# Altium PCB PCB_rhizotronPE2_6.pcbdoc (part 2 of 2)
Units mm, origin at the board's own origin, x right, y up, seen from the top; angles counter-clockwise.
Board outline 141.81 x 99.53 mm, 2 copper layers (Top Layer, Bottom Layer); 83 components, 239 nets, 496 pads, 263 vias.
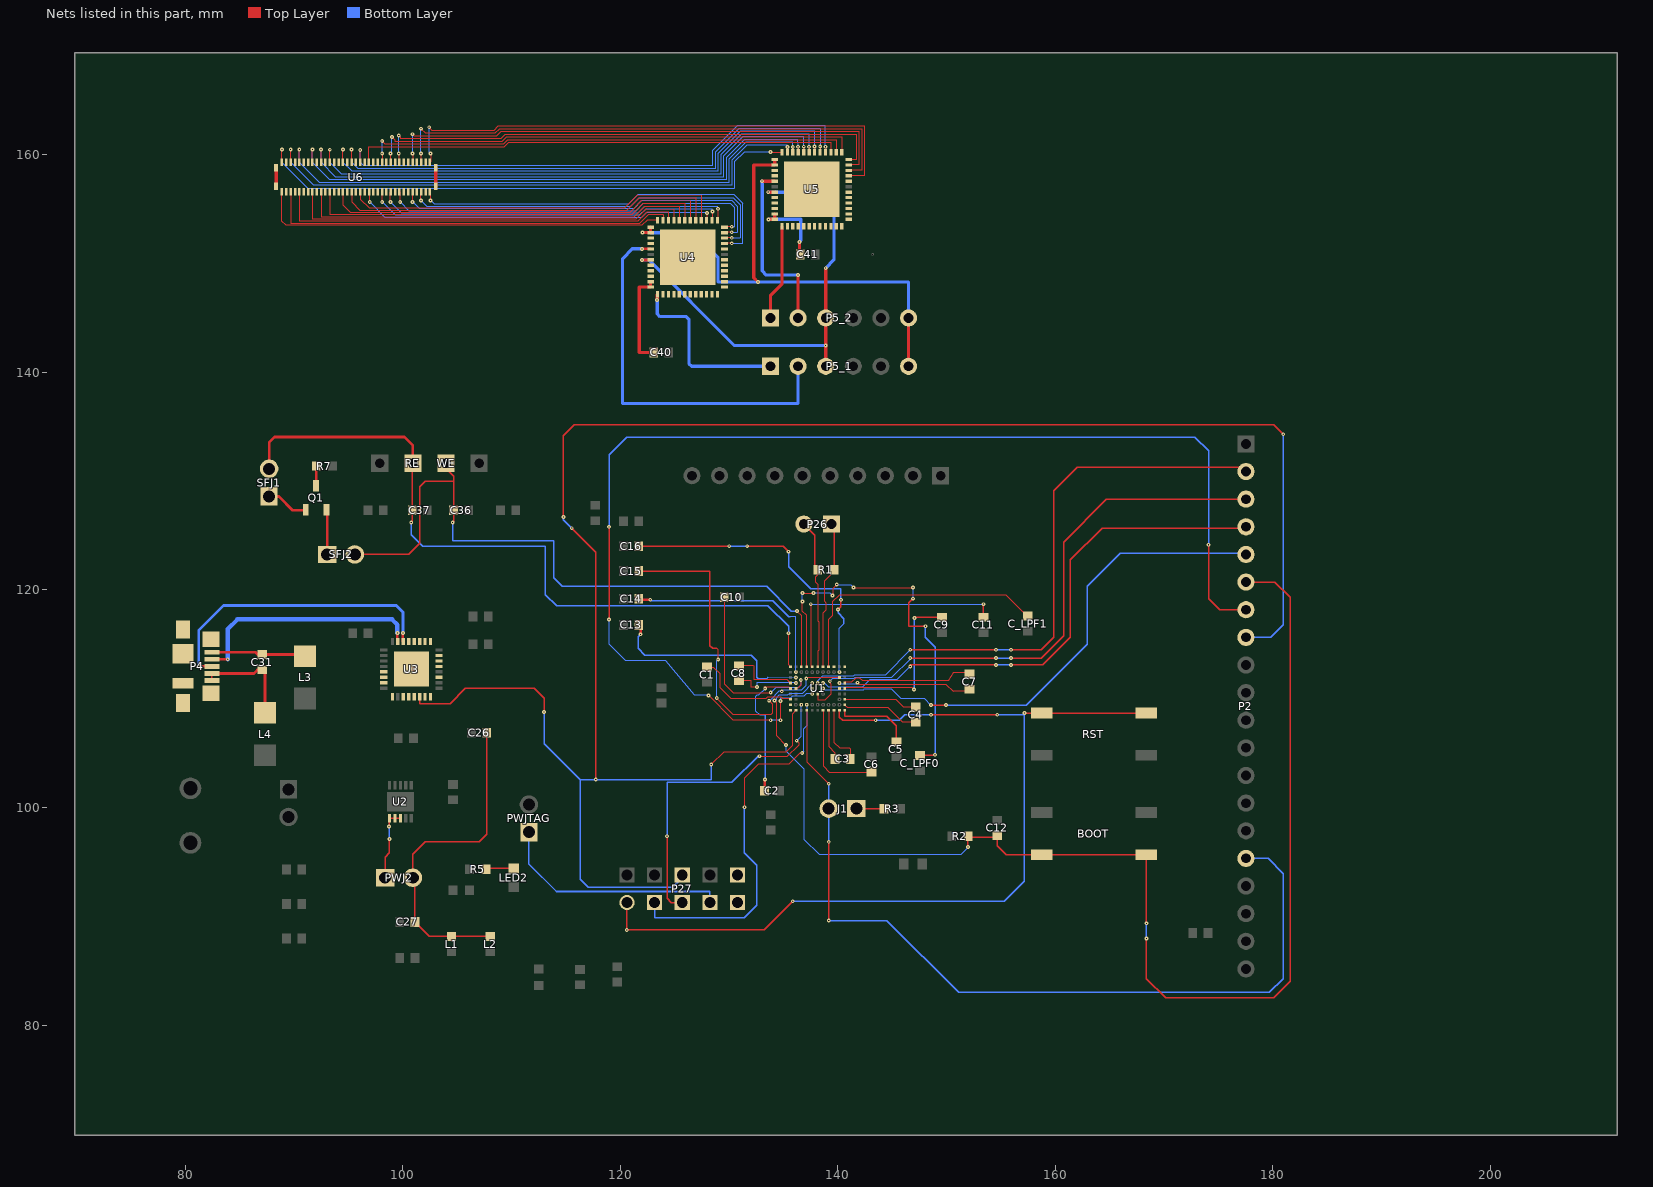
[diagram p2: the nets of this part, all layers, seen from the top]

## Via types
v1: diameter 0.35, hole 0.1, Top Layer to Bottom Layer, 263 vias

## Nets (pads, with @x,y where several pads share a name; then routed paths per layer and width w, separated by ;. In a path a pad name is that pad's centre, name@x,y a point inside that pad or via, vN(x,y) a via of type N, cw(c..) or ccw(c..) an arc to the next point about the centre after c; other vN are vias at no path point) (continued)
P0.11_SIN: P2.8 P27.6 U1.J2 U3.30 | length 187.6
  Top Layer w0.1: v1(128.369,103.953) 129.512,105.096 135.227,105.096 135.796,105.665 135.796,108.586 U1.J2@136.148,108.938
  Top Layer w0.125: U3.30@101.56,110.176 101.559,109.554 104.366,109.541 105.763,110.938 112.113,110.938 113.002,110.049 v1(113.002,108.779) ; v1(114.78,126.686) 114.78,134.179 115.796,135.195 180.058,135.195 v1(180.947,134.306) ; v1(115.542,125.67) 117.746,123.465 v1(117.746,102.556)
  Bottom Layer w0.125: v1(113.002,108.779) 113.002,105.858 116.304,102.556 ; v1(114.78,126.686) 114.78,126.432 v1(115.542,125.67) ; P27.6@125.702,93.793 125.702,93.539 124.813,92.65 117.066,92.65 116.304,93.412 116.304,102.556 ; v1(128.369,103.953) 128.369,102.556 v1(117.746,102.556) 116.304,102.556 ; P2.8@177.518,115.637 179.804,115.637 180.947,116.78 v1(180.947,134.306)
P1.0: P2.7 U1.F5 | length 115.1
  Top Layer w0.1: v1(128.115,110.303) 130.401,108.017 v1(133.83,108.017) ; v1(134.719,108.017) v1@134.719,109.795
  Top Layer w0.125: v1(118.971,117.288) v1(118.971,125.797) ; v1(174.089,124.146) 174.089,119.193 175.105,118.177 P2.7@177.518,118.177
  Bottom Layer w0.1: v1(118.971,117.288) 118.971,115.002 120.495,113.478 124.178,113.478 126.845,110.303 127.099,110.303 v1(128.115,110.303) ; v1(133.83,108.017) v1(134.719,108.017) ; v1@134.719,109.795 134.719,110.049 135.647,110.049 135.833,110.236 136.89,110.236 137.092,110.438 U1.F5@137.648,110.438
  Bottom Layer w0.125: v1(118.971,125.797) 118.971,132.401 120.622,134.052 172.819,134.052 174.089,132.782 v1(174.089,124.146)
  other v1: 134.719,109.786
P1.1: BOOT.1 BOOT.2 C12.2 P2.6 R2.1 U1.D5 | length 118.6
  Top Layer w0.1: v1(134.187,109.819) 134.338,109.668 134.338,106.62 v1(135.227,105.731)
  Top Layer w0.125: v1@151.967,96.357 151.967,97.246 154.493,97.246 C12.2@154.658,97.411 154.658,96.46 155.465,95.653 BOOT.2@158.748,95.653 BOOT.1@168.348,95.653 168.348,89.374 v1(168.374,89.348) ; v1(168.374,87.951) 168.374,84.268 170.152,82.49 180.058,82.49 181.582,84.014 181.582,119.32 180.185,120.717 P2.6@177.518,120.717
  Bottom Layer w0.1: v1(134.187,109.819) 134.238,109.819 134.338,109.919 134.338,110.049 134.592,110.303 135.354,110.303 135.524,110.473 136.727,110.473 137.648,111.394 U1.D5@137.648,111.438 ; v1(135.227,105.731) 135.227,105.223 136.878,103.572 136.878,97.095 138.275,95.698 151.356,95.698 151.968,96.31 v1(151.967,96.357)
  Bottom Layer w0.125: v1(168.374,87.951) v1(168.374,89.348)
P1.2_SCLK1: P2.5 U1.E7 | length 48.5
  Top Layer w0.125: v1(148.562,109.414) v1(149.959,109.414)
  Bottom Layer w0.1: U1.E7@138.648,110.938 138.748,110.838 142.383,110.838 142.438,110.893 144.924,110.893 145.768,110.049 147.927,110.049 v1(148.562,109.414)
  Bottom Layer w0.125: v1(149.959,109.414) 157.325,109.414 162.913,115.002 162.913,120.336 165.961,123.384 177.391,123.384 P2.5@177.518,123.257
P1.3_MOSI1: P2.4 U1.D7 | length 49.3
  Top Layer w0.125: v1(146.657,112.97) 146.657,113.097 v1(154.531,113.097) ; v1(155.928,113.097) 158.849,113.097 161.389,115.637 161.389,122.749 164.31,125.67 177.391,125.67 P2.4@177.518,125.797
  Bottom Layer w0.1: U1.D7@138.648,111.438 138.791,111.438 139.116,111.113 142.308,111.113 142.962,111.766 145.453,111.766 v1(146.657,112.97)
  Bottom Layer w0.125: v1(154.531,113.097) v1(155.928,113.097)
P1.4_MISO1: P2.3 U1.F6 | length 53.5
  Top Layer w0.1: U1.F6@138.148,110.438 138.148,109.909 138.849,109.909 139.394,110.454 139.394,111.343 139.267,111.469 v1(139.267,111.597)
  Top Layer w0.125: v1(146.657,113.732) v1(154.531,113.732) ; v1(155.928,113.732) 158.722,113.732 160.754,115.764 160.754,124.4 164.691,128.337 P2.3@177.518,128.337
  Bottom Layer w0.1: v1(139.267,111.597) 139.536,111.866 141.509,111.866 141.61,111.967 144.971,111.967 v1@146.741,113.737
  Bottom Layer w0.125: v1(154.531,113.732) v1(155.928,113.732)
P1.5_CS: P2.2 U1.D6 | length 55.8
  Top Layer w0.125: v1(146.657,114.494) v1(154.531,114.494) ; v1(155.928,114.494) 158.722,114.494 159.865,115.637 159.865,129.099 162.024,131.258 177.137,131.258 P2.2@177.518,130.877
  Bottom Layer w0.1: U1.D6@138.148,111.438 138.124,111.462 138.124,111.607 138.583,112.067 141.427,112.067 141.527,112.167 144.35,112.167 v1(146.657,114.494)
  Bottom Layer w0.125: v1(154.531,114.494) v1(155.928,114.494)
P2.4: J1.2 P2.16 U1.J4 | length 78.9
  Top Layer w0.1: U1.J4@137.148,108.938 137.147,104.192 v1(139.164,102.175)
  Top Layer w0.125: v1(139.164,89.602) v1(139.164,96.841)
  Bottom Layer w0.125: v1(139.164,89.602) 144.498,89.602 151.102,82.998 179.677,82.998 180.947,84.268 180.947,93.92 179.55,95.317 P2.16@177.518,95.317 ; v1(139.164,96.841) J1.2@139.164,99.889 v1(139.164,102.175)
P4_1: C31.2 L3.1 P4.1 | length 8.7
  Top Layer w0.254: P4.1@82.467,114.27 86.459,114.27 86.678,114.051 C31.2@87.094,114.051 90.884,114.051 L3.1@91.031,113.904
P4_4: C31.1 L4.1 P4.4 P4.5 | length 9.5
  Top Layer w0.125: P4.5@82.467,111.67 P4.4@82.467,112.32
  Top Layer w0.254: P4.4@82.467,112.32 86.332,112.32 86.663,112.651 C31.1@87.094,112.651 87.348,112.397 L4.1@87.348,108.697
P27_9: P27.9
P27_10: P27.10
PWJ2_2: C26.2 C27.2 L1.1 L2.1 PWJ2.2 | length 30.7
  Top Layer w0.125: C26.2@107.733,106.874 107.734,97.537 107.035,96.841 102.08,96.841 100.937,95.698 PWJ2.2@100.937,93.539 101.129,93.347 C27.2@101.129,89.475 102.461,88.143 L1.1@104.493,88.143 L2.1@108.049,88.143
PWJTAG_1: P27.7 PWJTAG.1 | length 21.6
  Bottom Layer w0.152: PWJTAG.1@111.605,97.73 111.605,94.809 114.145,92.269 128.242,92.269 P27.7@128.242,91.253
Q1_1: Q1.1 SFJ1.1 | length 3.9
  Top Layer w0.254: SFJ1.1@87.729,128.591 88.618,128.591 89.888,127.321 91.097,127.321 Q1.1@91.097,127.361
Q1_2: Q1.2 SFJ2.1 | length 4.1
  Top Layer w0.254: Q1.2@92.997,127.363 93.063,127.297 SFJ2.1@93.063,123.257
Q1_3: Q1.3 R7.1 | length 1.8
  Top Layer w0.254: Q1.3@92.047,129.565 R7.1@92.056,131.385
R3_2: J1.1 R3.2 | length 2.5
  Top Layer w0.125: J1.1@141.704,99.889 R3.2@144.253,99.889
R5_1: LED2.1 R5.1 | length 2.6
  Top Layer w0.125: R5.1@107.659,94.301 107.747,94.389 LED2.1@110.208,94.389
RE0: C37.1 RE.1 SFJ1.2 U1.A1 | length 69
  Top Layer w0.1: v1(135.481,116.018) 135.481,113.105 U1.A1@135.648,112.938
  Top Layer w0.125: v1(100.786,126.202) 100.872,126.288 C37.1@100.872,127.321 100.872,131.574 RE.1@100.937,131.639
  Top Layer w0.254: SFJ1.2@87.729,131.131 87.729,133.544 88.237,134.052 100.175,134.052 100.937,133.29 RE.1@100.937,131.639
  Bottom Layer w0.125: v1(100.786,126.202) 100.786,125.059 101.826,124.019 113.129,124.019 113.129,119.574 114.145,118.558 133.576,118.558 135.481,116.653 v1(135.481,116.018)
RE1: U1.A11
RESET: P27.1 RST.1 RST.2 U1.J10 | length 85.5
  Top Layer w0.125: P27.1@120.622,91.253 120.598,91.229 v1(120.598,88.737) 133.219,88.737 v1(135.862,91.38) ; U1.J10@140.148,108.938 140.148,108.303 140.434,108.017 v1(143.482,108.017) ; v1(148.562,108.525) v1(154.658,108.525) ; v1@157.174,108.676 168.327,108.676 RST.2@168.348,108.697
  Bottom Layer w0.125: v1(135.862,91.38) 155.293,91.38 157.129,93.216 v1@157.129,108.525 ; v1(143.482,108.017) 145.641,108.017 146.149,108.525 v1(148.562,108.525) ; v1(154.658,108.525) v1@157.129,108.525 ; v1@157.174,108.676 157.129,108.632 v1@157.129,108.525
  other v1: 157.174,108.676
SCLK: P5_1.3 P5_2.3 U4.19 U5.19 | length 43.9
  Top Layer w0.3: v1(121.995,150.332) 122.782,150.332 U4.19@122.786,150.336 ; v1(133.605,156.559) U5.19@134.216,156.559 ; P5_1.3@138.886,140.553 v1(138.886,142.458) P5_2.3@138.886,144.998 v1(138.886,149.57)
  Bottom Layer w0.3: v1(121.995,150.332) 122.63,150.332 130.504,142.458 v1(138.886,142.458) ; v1@133.607,156.56 139.648,156.56 139.648,150.332 v1(138.886,149.57)
SE0: C36.1 SFJ2.2 U1.A3 WE.1 | length 64
  Top Layer w0.1: v1(136.243,118.05) 136.648,117.645 U1.A3@136.648,112.938
  Top Layer w0.125: SFJ2.2@95.603,123.257 100.556,123.257 101.572,124.273 101.572,129.48 102.09,129.998 104.681,129.998 ; WE.1@103.985,131.639 103.985,131.131 104.682,130.434 C36.1@104.682,127.321 104.682,126.288 v1(104.596,126.202)
  Bottom Layer w0.125: v1(104.596,126.202) 104.62,126.178 104.62,124.527 113.891,124.527 113.891,121.098 114.653,120.336 133.449,120.336 135.735,118.05 v1(136.243,118.05)
SE1: U1.A9
SWCLK: P27.5 U1.H3 | length 29.7
  Top Layer w0.1: v1(132.814,104.715) 135.354,104.715 136.4,105.731 136.4,105.955 v1@136.219,106.136
  Top Layer w0.125: v1(124.305,97.349) 124.305,91.634 124.686,91.253 P27.5@125.702,91.253
  Bottom Layer w0.1: v1@136.219,106.136 136.648,106.565 U1.H3@136.648,109.438
  Bottom Layer w0.125: v1(124.305,97.349) 124.305,102.302 130.274,102.302 132.687,104.715 v1(132.814,104.715)
  other v1: 136.219,106.136
SWDIO: P27.3 U1.H4 | length 34.3
  Top Layer w0.1: v1(131.417,100.016) 131.417,102.683 132.687,103.953 135.481,103.953 136.521,104.993 v1(136.727,104.993)
  Bottom Layer w0.1: v1(136.727,104.993) 136.878,105.144 136.878,107.255 137.148,107.525 U1.H4@137.148,109.438
  Bottom Layer w0.125: P27.3@123.162,91.253 123.162,89.856 131.417,89.856 132.56,90.999 132.56,94.682 131.417,95.825 v1(131.417,100.016)
SYNC1: P5_1.2 U4.17 | length 35.8
  Top Layer w0.225: v1(121.995,151.348) 122.774,151.348 U4.17@122.786,151.336
  Bottom Layer w0.3: v1@121.994,151.347 121.106,151.347 120.217,150.459 120.217,137.124 136.346,137.124 P5_1.2@136.346,140.553
SYNC2: P5_2.2 U5.17 | length 16.8
  Top Layer w0.3: v1(133.044,157.571) 134.204,157.571 U5.17@134.216,157.559 ; P5_2.2@136.346,144.998 v1(136.346,148.935)
  Bottom Layer w0.3: v1(133.044,157.571) 133.044,149.316 133.425,148.935 v1(136.346,148.935)
TU4: P5_1.1 U4.25 | length 16.6
  Top Layer w0.3: v1(123.392,146.649) 123.392,147.142 U4.25@123.436,147.186
  Bottom Layer w0.3: v1(123.392,146.649) 123.392,145.379 123.646,145.125 126.059,145.125 126.313,144.871 126.313,140.807 126.567,140.553 P5_1.1@133.806,140.553
TU5: P5_2.1 U5.25 | length 8.8
  Top Layer w0.3: P5_2.1@133.806,144.998 133.806,147.03 134.865,148.089 U5.25@134.866,153.409
U1_A4: C_LPF0.2 U1.A4 | length 36.9
  Top Layer w0.1: v1(136.751,118.939) 136.751,118.05 137.148,117.652 U1.A4@137.148,112.938 ; v1(136.751,119.701) v1(137.767,119.701) ; v1@139.521,119.471 139.521,120.106 v1@139.902,120.487 ; v1(141.45,120.209) v1(146.911,120.209)
  Top Layer w0.125: v1(146.911,119.193) 146.53,118.812 146.53,116.653 v1(148.054,116.653) ; C_LPF0.2@147.546,104.78 148.881,104.78 v1(148.943,104.842)
  Bottom Layer w0.1: v1(136.751,118.939) v1(136.751,119.701) ; v1(137.767,119.701) 139.291,119.701 v1@139.521,119.471 ; v1@139.902,120.487 141.172,120.487 v1(141.45,120.209) ; v1(146.911,119.193) v1(146.911,120.209)
  Bottom Layer w0.125: v1(148.054,116.653) 148.054,115.637 148.943,114.748 v1(148.943,104.842)
  other v1: 139.521,119.471 139.902,120.487
U1_A5: C11.2 U1.A5 | length 22.8
  Top Layer w0.1: v1(137.513,118.685) 137.513,112.937 U1.A5@137.647,112.937
  Top Layer w0.125: C11.2@153.388,117.48 v1(153.388,118.685)
  Bottom Layer w0.1: v1(137.513,118.685) v1@153.261,118.685
U1_A6: P26.2 R1.1 U1.A6 | length 14
  Top Layer w0.1: U1.A6@138.157,112.938 138.157,114.346 138.251,114.44 138.251,117.067 138.157,117.162 138.157,120.515 137.971,120.7 137.971,121.226 138.157,121.412 R1.1@138.157,121.86
  Top Layer w0.125: P26.2@136.878,126.051 137.894,125.035 137.894,121.86 R1.1@138.157,121.86
U1_A7: P26.1 R1.2 U1.A7 | length 13.8
  Top Layer w0.1: U1.A7@138.656,112.937 138.656,117.905 138.939,118.188 138.939,118.783 138.783,118.939 138.783,120.844 139.664,121.725 R1.2@139.663,121.86
  Top Layer w0.125: P26.1@139.418,126.051 139.663,125.805 R1.2@139.663,121.86
U1_A8: C_LPF1.2 U1.A8 | length 25.1
  Top Layer w0.1: U1.A8@139.164,112.937 139.164,117.288 139.545,117.669 139.545,118.939 140.18,119.574 155.42,119.574 157.386,117.608 C_LPF1.2@157.452,117.607
U1_D1: C8.1 U1.D1 | length 6.1
  Top Layer w0.1: C8.1@130.909,113.035 132.244,113.035 132.306,112.97 132.306,111.753 135.333,111.753 U1.D1@135.648,111.438
U1_D2: C8.2 U1.D2 | length 6.2
  Top Layer w0.1: C8.2@130.909,111.634 132.052,111.634 132.052,111.065 v1(132.56,111.065)
  Bottom Layer w0.1: v1(132.56,111.065) 132.56,111.446 U1.D2@136.141,111.446
U1_D10: C7.2 U1.D10 | length 12.6
  Top Layer w0.1: v1(141.807,111.47) 141.934,111.343 149.935,111.343 150.594,110.684 152.118,110.684 C7.2@152.118,110.872
  Bottom Layer w0.1: U1.D10@140.148,111.438 140.248,111.338 141.675,111.338 v1(141.807,111.47)
U1_D11: C7.1 U1.D11 | length 12.2
  Top Layer w0.1: U1.D11@140.647,111.507 141.24,111.507 141.627,111.893 142.04,111.893 142.3,111.634 150.158,111.634 150.594,112.396 152.118,112.396 C7.1@152.118,112.335
U1_E1: C2.1 U1.E1 | length 13
  Top Layer w0.1: 133.195,111.065 135.521,111.065 U1.E1@135.648,110.938
  Top Layer w0.225: C2.1@133.257,101.54 133.298,101.581 v1(133.298,102.58)
  Bottom Layer w0.1: 133.322,108.525 132.814,108.525 132.433,108.906 132.433,110.176 132.56,110.303 132.687,110.303 v1@133.322,110.928
  Bottom Layer w0.125: v1@133.297,102.58 133.322,102.605 133.322,108.525
  other v1: 133.322,110.929
U1_E2: C10.2 U1.E2 | length 17.2
  Top Layer w0.1: C10.2@129.574,119.32 129.573,111.385 130.401,110.557 v1(133.83,110.557) ; U1.E2@136.148,110.938 136.322,110.938 136.6,111.216 v1(136.6,111.724)
  Bottom Layer w0.1: v1(133.83,110.557) 134.274,111.001 136.385,111.001 136.6,111.216 v1(136.6,111.724)
U1_E5: U1.E5
U1_E10: U1.E10
U1_E11: C9.2 U1.E11 | length 15.6
  Top Layer w0.1: U1.E11@140.648,110.938 140.728,111.018 146.831,111.018 v1@147.014,110.835
  Top Layer w0.125: v1(147.038,117.415) 147.103,117.48 C9.2@149.578,117.48
  Bottom Layer w0.125: v1@147.014,110.835 147.014,117.391 v1(147.038,117.415)
  other v1: 147.014,110.835
U1_G1: C1.2 U1.G1 | length 9.8
  Top Layer w0.1: C1.2@127.988,112.908 128.557,112.909 129.131,112.335 129.131,111.065 130.147,110.049 133.426,110.049 133.558,110.181 134.775,110.181 134.908,110.049 135.649,110.049 U1.G1@135.649,109.922
U1_G11: C4.1 U1.G11 | length 6.8
  Top Layer w0.1: U1.G11@140.647,109.922 145.387,109.922 146.083,109.226 C4.1@147.165,109.225
U1_H11: C4.2 U1.H11 | length 7.2
  Top Layer w0.1: U1.H11@140.647,109.414 140.901,109.16 144.625,109.16 145.961,107.824 C4.2@147.165,107.824
U1_J7: C6.1 U1.J7 | length 9.8
  Top Layer w0.1: 138.648,103.833 139.23,103.252 C6.1@143.101,103.252 ; 138.658,103.834 U1.J7@138.658,108.938
U1_J8: C3.2 U1.J8 | length 4.7
  Top Layer w0.1: U1.J8@139.148,108.938 139.148,105.604 139.734,105.018 C3.2@139.734,104.461
U1_J9: C3.1 U1.J9 | length 5.6
  Top Layer w0.1: U1.J9@139.648,108.938 139.649,106.008 140.18,105.477 141.069,105.477 141.135,105.411 C3.1@141.134,104.461
U1_J11: C5.2 U1.J11 | length 7.1
  Top Layer w0.125: U1.J11@140.648,108.938 140.647,108.398 144.498,108.398 145.387,107.509 C5.2@145.387,106.05
U2_1: PWJ2.1 U2.1 U2.2 U2.3 | length 6.7
  Top Layer w0.125: PWJ2.1@98.397,93.539 98.397,95.444 98.778,95.825 v1(98.778,97.095) ; v1(98.754,98.262) 98.754,99 U2.2@99.294,99 U2.3@99.794,99
  Bottom Layer w0.125: v1(98.754,98.262) 98.778,98.238 v1(98.778,97.095)
U3_3: U3.3
U3_5: U3.5
U3_6: U3.6
U3_7: U3.7
U3_9: U3.9
U3_10: U3.10
U3_11: U3.11
U3_12: U3.12
U3_13: U3.13
U3_21: U3.21
U3_22: U3.22
U3_23: U3.23
U3_25: U3.25
U3_27: U3.27
U3_28: U3.28
U3_29: U3.29
U3_31: U3.31
U3_32: U3.32
U3_33: U3.33
U4_1: U4.1 U6.51 | length 33
  Top Layer w0.1: v1(98.881,155.666) 98.881,156.572 U6.51@98.906,156.597 ; U4.1@128.936,153.986 128.98,154.03 v1(128.98,155.031)
  Bottom Layer w0.1: v1(98.881,155.666) 99.877,154.67 121.634,154.67 122.249,155.285 128.98,155.285 v1(128.98,155.031)
U4_2: U4.2 U6.47 | length 33.1
  Top Layer w0.1: U6.47@98.106,156.597 98.119,156.584 v1(98.119,155.666) ; U4.2@128.436,153.986 128.472,154.022 v1(128.472,154.777)
  Bottom Layer w0.1: v1(98.119,155.666) 99.315,154.47 121.815,154.47 122.376,155.031 128.472,155.031 v1(128.472,154.777)
U4_3: U4.3 U6.41 | length 33.4
  Top Layer w0.1: U6.41@96.906,156.597 96.976,156.527 v1(96.976,155.666) ; U4.3@127.936,153.986 127.964,154.014 v1(127.964,154.65)
  Bottom Layer w0.1: v1(96.976,155.666) 98.373,154.269 121.995,154.269 122.376,154.65 v1(127.964,154.65)
U4_4: U4.4 U6.37 | length 35.1
  Top Layer w0.1: U6.37@96.106,156.597 96.106,155.92 96.912,155.114 120.427,155.114 121.614,156.301 127.436,156.281 U4.4@127.436,153.986
U4_5: U4.5 U6.33 | length 35.4
  Top Layer w0.1: U6.33@95.306,156.597 95.306,155.666 96.059,154.914 120.608,154.914 121.741,156.047 126.936,156.035 U4.5@126.936,153.986
U4_6: U4.6 U6.29 | length 35.7
  Top Layer w0.1: U6.29@94.506,156.597 94.506,155.412 95.205,154.713 120.915,154.713 121.995,155.793 126.436,155.789 U4.6@126.436,153.986
U4_7: U4.7 U6.23 | length 36.7
  Top Layer w0.1: U6.23@93.306,156.597 93.306,154.512 121.095,154.512 122.122,155.539 125.936,155.535 U4.7@125.936,153.986
U4_8: U4.8 U6.19 | length 36.9
  Top Layer w0.1: U6.19@92.506,156.597 92.506,154.312 121.276,154.312 122.249,155.285 125.436,155.273 U4.8@125.436,153.986
U4_9: U4.9 U6.15 | length 37.1
  Top Layer w0.1: U6.15@91.706,156.597 91.706,154.111 121.456,154.111 122.376,155.031 124.936,155.011 U4.9@124.936,153.986
U4_10: U4.10 U6.9 | length 37.7
  Top Layer w0.1: U6.9@90.506,156.597 90.506,153.91 121.636,153.91 122.503,154.777 124.408,154.777 124.436,154.749 U4.10@124.436,153.986
U4_11: U4.11 U6.5 | length 38
  Top Layer w0.1: U6.5@89.706,156.597 89.706,153.71 121.817,153.71 122.63,154.523 123.9,154.523 123.936,154.487 U4.11@123.936,153.986
U4_12: U4.12 U6.1 | length 37.6
  Top Layer w0.1: U6.1@88.906,156.597 88.906,153.888 89.286,153.509 121.997,153.509 122.474,153.986 U4.12@123.436,153.986
U4_15: U4.15
U4_16: U4.16
U4_20: U4.20
U4_21: U4.21
U4_22: U4.22
U4_23: C40.1 U4.23 U4.24 | length 8.9
  Top Layer w0.3: U4.23@122.786,148.336 U4.24@122.786,147.836 121.741,147.836 121.741,141.823 C40.1@123.073,141.823
U4_26: U4.26
U4_27: U4.27
U4_28: U4.28
U4_29: U4.29
U4_30: U4.30
U4_31: U4.31
U4_32: U4.32
U4_33: U4.33
U4_34: U4.34
U4_35: U4.35
U4_36: U4.36
U4_37: U4.37
U4_38: U4.38
U4_39: U4.39
U4_40: U4.40
U4_41: U4.41
U4_42: U4.42
U4_44: U4.44
U4_45: U4.45 U6.69 | length 35.7
  Top Layer w0.1: U6.69@102.506,156.597 102.564,156.539 v1(102.564,155.793) ; U4.45@129.586,151.836 129.606,151.856 v1(130.25,151.856)
  Bottom Layer w0.1: v1(102.564,155.793) 102.885,155.473 120.786,155.473 121.614,156.301 130.504,156.301 131.266,155.539 131.266,151.856 v1(130.25,151.856)
U4_46: U4.46 U6.65 | length 35.4
  Top Layer w0.1: v1(101.675,155.793) 101.675,156.566 U6.65@101.706,156.597 ; U4.46@129.586,152.336 129.614,152.364 v1(130.25,152.364)
  Bottom Layer w0.1: v1(101.675,155.793) 102.196,155.272 120.966,155.272 121.741,156.047 130.377,156.047 131.012,155.412 131.012,152.364 v1(130.25,152.364)
U4_47: U4.47 U6.61 | length 35.1
  Top Layer w0.1: U6.61@100.906,156.597 100.913,156.59 v1(100.913,155.666) ; U4.47@129.586,152.836 129.622,152.872 v1(130.25,152.872)
  Bottom Layer w0.1: v1(100.913,155.666) 101.507,155.072 121.274,155.072 121.995,155.793 130.25,155.793 130.758,155.285 130.758,152.872 v1(130.25,152.872)
U4_48: U4.48 U6.55 | length 35.2
  Top Layer w0.1: U6.55@99.706,156.597 99.77,156.533 v1(99.77,155.666) ; U4.48@129.586,153.336 129.63,153.38 v1(130.25,153.38)
  Bottom Layer w0.1: v1(99.77,155.666) 100.565,154.871 121.454,154.871 122.122,155.539 130.123,155.539 130.504,155.158 130.504,153.38 v1(130.25,153.38)
U4_49: U4.49
U5_1: U5.1 U6.52 | length 45.6
  Top Layer w0.1: v1(98.881,160.111) 98.881,159.332 U6.52@98.906,159.307 ; v1(99.008,161.635) 99.262,161.381 99.262,161.254 109.168,161.254 109.549,161.635 140.367,161.635 U5.1@140.367,160.21
  Bottom Layer w0.1: v1(98.881,160.111) 99.008,160.238 v1(99.008,161.635)
U5_2: U5.2 U6.48 | length 45.1
  Top Layer w0.1: U6.48@98.106,159.307 98.119,159.32 v1(98.119,160.111) ; v1(98.119,161.254) 98.373,161 109.295,161 109.676,161.381 139.866,161.381 U5.2@139.866,160.209
  Bottom Layer w0.1: v1@98.119,160.11 v1(98.119,161.254)
U5_3: U5.3 U6.42 | length 45
  Top Layer w0.1: U6.42@96.906,159.307 96.905,160.746 109.351,160.746 109.732,161.127 139.366,161.127 U5.3@139.366,160.21
U5_4: U5.4 U6.38 | length 50
  Top Layer w0.1: U6.38@96.106,159.307 v1(96.106,160.442) ; U5.4@138.866,160.209 138.874,160.217 v1(138.874,160.734)
  Bottom Layer w0.1: v1(96.106,160.442) 96.105,159.306 96.443,158.968 128.472,158.968 128.472,160.365 130.758,162.651 138.866,162.651 138.866,160.741 v1(138.874,160.734)
U5_5: U5.5 U6.34 | length 50.2
  Top Layer w0.1: U6.34@95.306,159.307 v1@95.306,160.466 ; U5.5@138.366,160.209 138.378,160.221 v1(138.378,160.746)
  Bottom Layer w0.1: v1(95.305,160.467) 95.305,159.306 95.897,158.714 128.726,158.714 128.726,160.238 130.885,162.397 138.38,162.397 v1(138.378,160.746)
U5_6: U5.6 U6.30 | length 50.5
  Top Layer w0.1: U6.30@94.506,159.307 v1(94.506,160.467) ; U5.6@137.866,160.209 v1(137.866,160.753)
  Bottom Layer w0.1: v1(94.506,160.467) 94.506,159.307 95.353,158.46 128.98,158.46 128.98,160.111 131.012,162.143 137.866,162.143 v1(137.866,160.753)
U5_7: U5.7 U6.24 | length 51.1
  Top Layer w0.1: U6.24@93.306,159.307 v1(93.306,160.464) ; U5.7@137.365,160.21 v1(137.365,160.737)
  Bottom Layer w0.1: v1(93.306,160.464) 93.306,159.306 94.406,158.206 129.234,158.206 129.234,159.984 131.139,161.889 137.361,161.889 v1(137.365,160.737)
U5_8: U5.8 U6.20 | length 51.4
  Top Layer w0.1: U6.20@92.506,159.307 v1(92.506,160.493) ; U5.8@136.867,160.21 v1(136.867,160.742)
  Bottom Layer w0.1: v1(92.506,160.493) 92.506,159.306 93.86,157.952 129.488,157.952 129.488,159.857 131.266,161.635 136.867,161.635 v1(136.867,160.742)
U5_9: U5.9 U6.16 | length 51.5
  Top Layer w0.1: U6.16@91.706,159.307 v1@91.706,160.471 ; v1(136.355,160.731) 136.355,160.22 U5.9@136.366,160.209
  Bottom Layer w0.1: v1(91.706,160.471) 91.706,159.306 93.313,157.698 129.742,157.698 129.742,159.73 131.393,161.381 136.34,161.381 v1(136.355,160.731)
U5_10: U5.10 U6.10 | length 52.2
  Top Layer w0.1: v1(90.499,160.492) 90.506,160.485 U6.10@90.506,159.307 ; U5.10@135.866,160.209 v1(135.866,160.721)
  Bottom Layer w0.1: v1(90.499,160.492) 90.507,160.484 90.507,159.306 92.369,157.444 129.996,157.444 129.996,159.603 131.52,161.127 135.866,161.127 v1(135.866,160.721)
U5_11: U5.11 U6.6 | length 52.4
  Top Layer w0.1: U6.6@89.706,159.307 v1(89.706,160.471) ; U5.11@135.366,160.209 v1(135.366,160.711)
  Bottom Layer w0.1: v1(89.706,160.471) 89.706,159.307 91.823,157.19 130.25,157.19 130.25,159.476 131.647,160.873 135.366,160.873 v1(135.366,160.711)
U5_12: U5.12 U6.2 | length 52.1
  Top Layer w0.1: U6.2@88.906,159.307 v1(88.906,160.482) ; v1(133.806,160.238) 133.835,160.209 U5.12@134.866,160.209
  Bottom Layer w0.1: v1(88.906,160.482) 88.906,159.307 91.277,156.936 130.504,156.936 130.504,159.349 131.393,160.238 v1@133.806,160.238
U5_15: U5.15
U5_16: U5.16
U5_20: U5.20
U5_21: U5.21
U5_22: U5.22
U5_23: C41.1 U5.23 U5.24 | length 7.3
  Top Layer w0.3: v1(133.641,154.059) U5.24@134.216,154.059 U5.23@134.216,154.559 ; v1(136.473,151.983) 136.473,150.902 C41.1@136.535,150.84
  Bottom Layer w0.3: v1(133.641,154.059) 136.6,154.059 136.6,152.11 v1@136.473,151.983
U5_26: U5.26
U5_27: U5.27
U5_28: U5.28
U5_29: U5.29
U5_30: U5.30
U5_31: U5.31
U5_32: U5.32
U5_33: U5.33
U5_34: U5.34
U5_35: U5.35
U5_36: U5.36
U5_37: U5.37
U5_38: U5.38
U5_39: U5.39
U5_40: U5.40
U5_41: U5.41
U5_42: U5.42
U5_44: U5.44
U5_45: U5.45 U6.70 | length 49.6
  Top Layer w0.1: v1(102.437,162.524) 102.691,162.27 108.406,162.27 108.787,162.651 142.442,162.651 142.442,158.059 U5.45@141.016,158.059 ; U6.70@102.506,159.307 102.564,159.365 v1(102.564,160.111)
  Bottom Layer w0.1: v1(102.437,162.524) 102.437,160.238 v1(102.564,160.111)
U5_46: U5.46 U6.66 | length 48.9
  Top Layer w0.1: v1(101.675,160.111) 101.675,159.338 U6.66@101.706,159.307 ; v1(101.675,162.397) 102.056,162.016 108.533,162.016 108.914,162.397 142.188,162.397 142.188,158.559 U5.46@141.016,158.559
  Bottom Layer w0.1: v1(101.675,160.111) v1(101.675,162.397)
U5_47: U5.47 U6.62 | length 47.8
  Top Layer w0.1: U6.62@100.906,159.307 100.913,159.314 v1(100.913,160.111) ; v1(100.913,161.889) 101.04,161.762 108.66,161.762 109.041,162.143 141.934,162.143 141.934,159.095 141.898,159.059 U5.47@141.016,159.059
  Bottom Layer w0.1: v1@100.913,160.11 v1@100.913,161.889
U5_48: U5.48 U6.56 | length 47.8
  Top Layer w0.1: v1(99.643,160.111) 99.643,159.37 U6.56@99.706,159.307 ; v1(99.643,161.762) 99.77,161.635 99.77,161.508 109.041,161.508 109.422,161.889 141.68,161.889 141.68,159.56 U5.48@141.017,159.56
  Bottom Layer w0.1: v1(99.643,160.111) v1(99.643,161.762)
U5_49: U5.49
U6_3: U6.3
U6_4: U6.4
U6_7: U6.7
U6_8: U6.8
U6_11: U6.11
U6_12: U6.12
U6_13: U6.13
U6_14: U6.14
U6_17: U6.17
U6_18: U6.18
U6_21: U6.21
U6_22: U6.22
U6_25: U6.25
U6_26: U6.26
U6_27: U6.27
U6_28: U6.28
U6_31: U6.31
U6_32: U6.32
U6_35: U6.35
U6_36: U6.36
U6_39: U6.39
U6_40: U6.40
U6_43: U6.43
U6_44: U6.44
U6_45: U6.45
U6_46: U6.46
U6_49: U6.49
U6_50: U6.50
U6_53: U6.53
U6_54: U6.54
U6_57: U6.57
U6_58: U6.58
U6_59: U6.59
U6_60: U6.60
U6_63: U6.63
U6_64: U6.64
U6_67: U6.67
U6_68: U6.68
U6_SHLD: U6.71 U6.72 U6.73 U6.SHLD | length 3.4
  Top Layer w0.3: U6.73@88.371,157.092 U6.SHLD@88.371,158.812 ; U6.71@103.041,157.092 U6.72@103.041,158.812
USBD+: P4.3 U3.14 | length 27.2
  Top Layer w0.225: v1(81.251,112.969) P4.3@82.467,112.97 ; v1(100.024,116.042) 100.024,115.292 U3.14@100.06,115.256
  Bottom Layer w0.25: v1(81.251,112.969) 81.251,116.271 83.537,118.557 99.412,118.557 100.024,117.945 v1@100.024,116.041
USBD-: P4.2 U3.15 | length 22
  Top Layer w0.225: P4.2@82.467,113.62 v1(83.919,113.62) ; v1(99.516,116.042) 99.516,115.3 U3.15@99.56,115.256
  Bottom Layer w0.4: v1(83.919,113.62) 83.919,116.399 84.808,117.288 99.032,117.288 99.517,116.803 v1(99.516,116.042)
VBIAS0: C13.2 U1.C2 | length 18.9
  Top Layer w0.225: C13.2@121.703,116.78 121.868,116.615 v1(121.868,115.915)
  Bottom Layer w0.1: 133.322,111.827 133.449,111.827 133.576,111.954 U1.C2@136.148,111.938
  Bottom Layer w0.125: v1@121.868,115.915 121.638,115.685 121.638,114.621 122.273,113.986 132.052,113.986 132.56,113.478 132.56,111.954 132.687,111.827 133.322,111.827
VBIAS1: C15.2 pad.24 U1.C10 | length 33.6
  Top Layer w0.1: v1(128.877,110.049) 130.401,108.525 133.83,108.525 133.957,108.652 133.957,109.541 pad.24@133.679,109.819 ; 128.877,114.621 129.004,114.494 v1(129.004,113.605) ; v1(137.108,111.851) 137.244,111.987 140.1,111.987 U1.C10@140.148,111.938
  Top Layer w0.125: C15.2@121.703,121.733 128.242,121.733 128.242,114.875 128.496,114.621 128.877,114.621
  Bottom Layer w0.1: v1(128.877,110.049) 128.877,113.478 v1(129.004,113.605) ; pad.24@133.679,109.819 133.73,109.819 133.83,109.919 133.83,109.922 134.582,110.674 v1(134.846,110.674) 134.973,110.801 136.692,110.801 137.108,111.216 v1(137.108,111.851)
VDD: P5_1.6 P5_2.6 U4.13 U4.14 U5.13 U5.14 | length 50
  Top Layer w0.3: v1(122.036,152.843) U4.14@122.786,152.843 ; U4.14@122.786,152.836 U4.14@122.786,152.843 ; U4.13@122.786,153.336 U4.14@122.786,152.843 ; v1(132.663,148.3) 132.282,148.681 132.282,159.059 U5.14@134.216,159.059 U5.13@134.216,159.559 ; P5_1.6@146.506,140.553 P5_2.6@146.506,144.998
  Bottom Layer w0.3: v1(122.036,152.843) 122.778,152.843 122.785,152.837 126.73,152.837 128.98,150.586 128.98,148.3 v1(132.663,148.3) 146.506,148.3 P5_2.6@146.506,144.998
VZERO0: C14.2 U1.B2 | length 20.2
  Top Layer w0.225: C14.2@121.703,119.193 121.806,119.09 v1(122.757,119.09)
  Bottom Layer w0.1: 135.608,117.542 136.148,117.542 U1.B2@136.148,112.43
  Bottom Layer w0.125: v1(122.757,119.09) 122.828,119.02 134.003,119.02 135.481,117.542 135.608,117.542
VZERO1: C16.2 U1.B10 | length 29.2
  Top Layer w0.125: C16.2@121.703,124.019 v1(130.02,124.019) ; v1(131.671,124.019) 134.973,124.019 v1(135.481,123.511) ; v1@140.029,118.201 140.283,118.455 v1@140.283,119.09
  Bottom Layer w0.1: U1.B10@140.148,112.438 140.148,116.494 140.561,116.907
  Bottom Layer w0.125: v1(130.02,124.019) v1(131.671,124.019) ; v1(135.481,123.511) 135.481,122.114 137.513,120.082 140.283,120.082 v1(140.283,119.09) ; v1@140.029,118.201 140.029,117.897 140.561,117.365 140.561,116.907
  other v1: 140.029,118.201
XTALI: U1.H1
XTALO: U1.J1
"": P4.6 P4.7 P4.8 P4.9 P4.10 P4.GND

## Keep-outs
Board Outline Layer:
  lines w0.1 net "": 76.272,140.426 76.275,80.228 77.291,79.212 203.783,79.72 204.291,79.72 205.307,80.736 205.307,152.872 ; 76.275,140.426 114.502,140.426 114.502,149.316 76.283,149.316 76.275,152.872 ; 76.275,152.872 77.291,153.888 80.847,153.888 83.387,153.888 83.387,155.92 83.387,158.587 87.832,163.032 90.499,163.032 180.923,163.032 188.035,155.92 188.035,153.888 204.291,153.888 205.307,152.872 ; 76.275,152.872 76.275,152.872 ; 205.307,152.872 205.307,152.872

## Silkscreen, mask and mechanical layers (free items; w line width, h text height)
Mechanical Layer:
  circle w0.025 net "": c78.561,82.26 r1.016
  circle w0.025 net "": c78.561,151.26 r1.016
  circle w0.025 net "": c202.561,151.26 r1.016
  circle w0.025 net "": c202.561,82.26 r1.016
Mech6:
  text "." at 76.897,79.077 h3.4
  text "X = 0.1mm, Y = 0 mm" at 76.289,76.601 h2.17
